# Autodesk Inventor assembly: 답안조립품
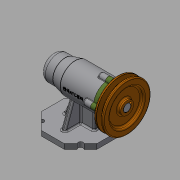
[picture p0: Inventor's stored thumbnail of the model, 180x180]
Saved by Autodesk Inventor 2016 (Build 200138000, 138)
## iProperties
Created: 2019-12
Part Number: 답안조립품
Material: 일반
Document SubType Name: Weldment
Designer: Administrator
Weld Material: Welded Aluminum-6061
Author: Administrator
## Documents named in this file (12)
- C:\Users\Administrator\Desktop\491204V1057\답안조립품.iam
- C:\Users\Administrator\Desktop\491204V1057\본체.ipt
- C:\Users\Administrator\Desktop\491204V1057\축.ipt
- C:\Users\Administrator\Desktop\491204V1057\키 5 x 5 x 16.ipt
- C:\Users\Administrator\Desktop\491204V1057\베어링 6004.ipt
- C:\Users\Administrator\Desktop\491204V1057\베어링 51202.ipt
- C:\Users\Administrator\Desktop\491204V1057\어댑터슬리브.ipt
- C:\Users\Administrator\Desktop\491204V1057\볼트 M4.ipt
- C:\Users\Administrator\Desktop\491204V1057\커버.ipt
- C:\Users\Administrator\Desktop\491204V1057\오일 실.ipt
- C:\Users\Administrator\Desktop\491204V1057\멈춤나사 M3.ipt
- C:\Users\Administrator\Desktop\491204V1057\V벨트풀리.ipt
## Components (1 placed, 1 different names)
1. V벨트풀리:1
